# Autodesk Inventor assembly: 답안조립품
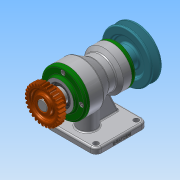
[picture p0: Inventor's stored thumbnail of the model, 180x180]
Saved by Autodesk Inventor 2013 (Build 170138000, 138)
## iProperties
Created: 2019-01
Part Number: 답안조립품
Document SubType Name: Assembly
Designer: Administrator
Author: Administrator
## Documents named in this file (15)
- C:\Users\Administrator\Desktop\490107V1040\답안조립품.iam
- C:\Users\Administrator\Desktop\490107V1040\본체.ipt
- C:\Users\Administrator\Desktop\490107V1040\V-벨트풀리.ipt
- C:\Users\Administrator\Desktop\490107V1040\뒤커버.ipt
- C:\Users\Administrator\Desktop\490107V1040\멈춤나사 M3.ipt
- C:\Users\Administrator\Desktop\490107V1040\베어링 6203.ipt
- C:\Users\Administrator\Desktop\490107V1040\베어링 6205.ipt
- C:\Users\Administrator\Desktop\490107V1040\볼트 M4.ipt
- C:\Users\Administrator\Desktop\490107V1040\스퍼기어.ipt
- C:\Users\Administrator\Desktop\490107V1040\앞커버.ipt
- C:\Users\Administrator\Desktop\490107V1040\오일 실 17 30 8.ipt
- C:\Users\Administrator\Desktop\490107V1040\오일 실 25 38 8.ipt
- C:\Users\Administrator\Desktop\490107V1040\축.ipt
- C:\Users\Administrator\Desktop\490107V1040\키 5 x 5 x 20.ipt
- C:\Users\Administrator\Desktop\490107V1040\키 6 x 6 x 18.ipt
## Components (1 placed, 1 different names)
1. V-벨트풀리:1 — 플러쉬:2
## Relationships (1: Flush 1)
- 플러쉬:2 [Flush]: V-벨트풀리:1
